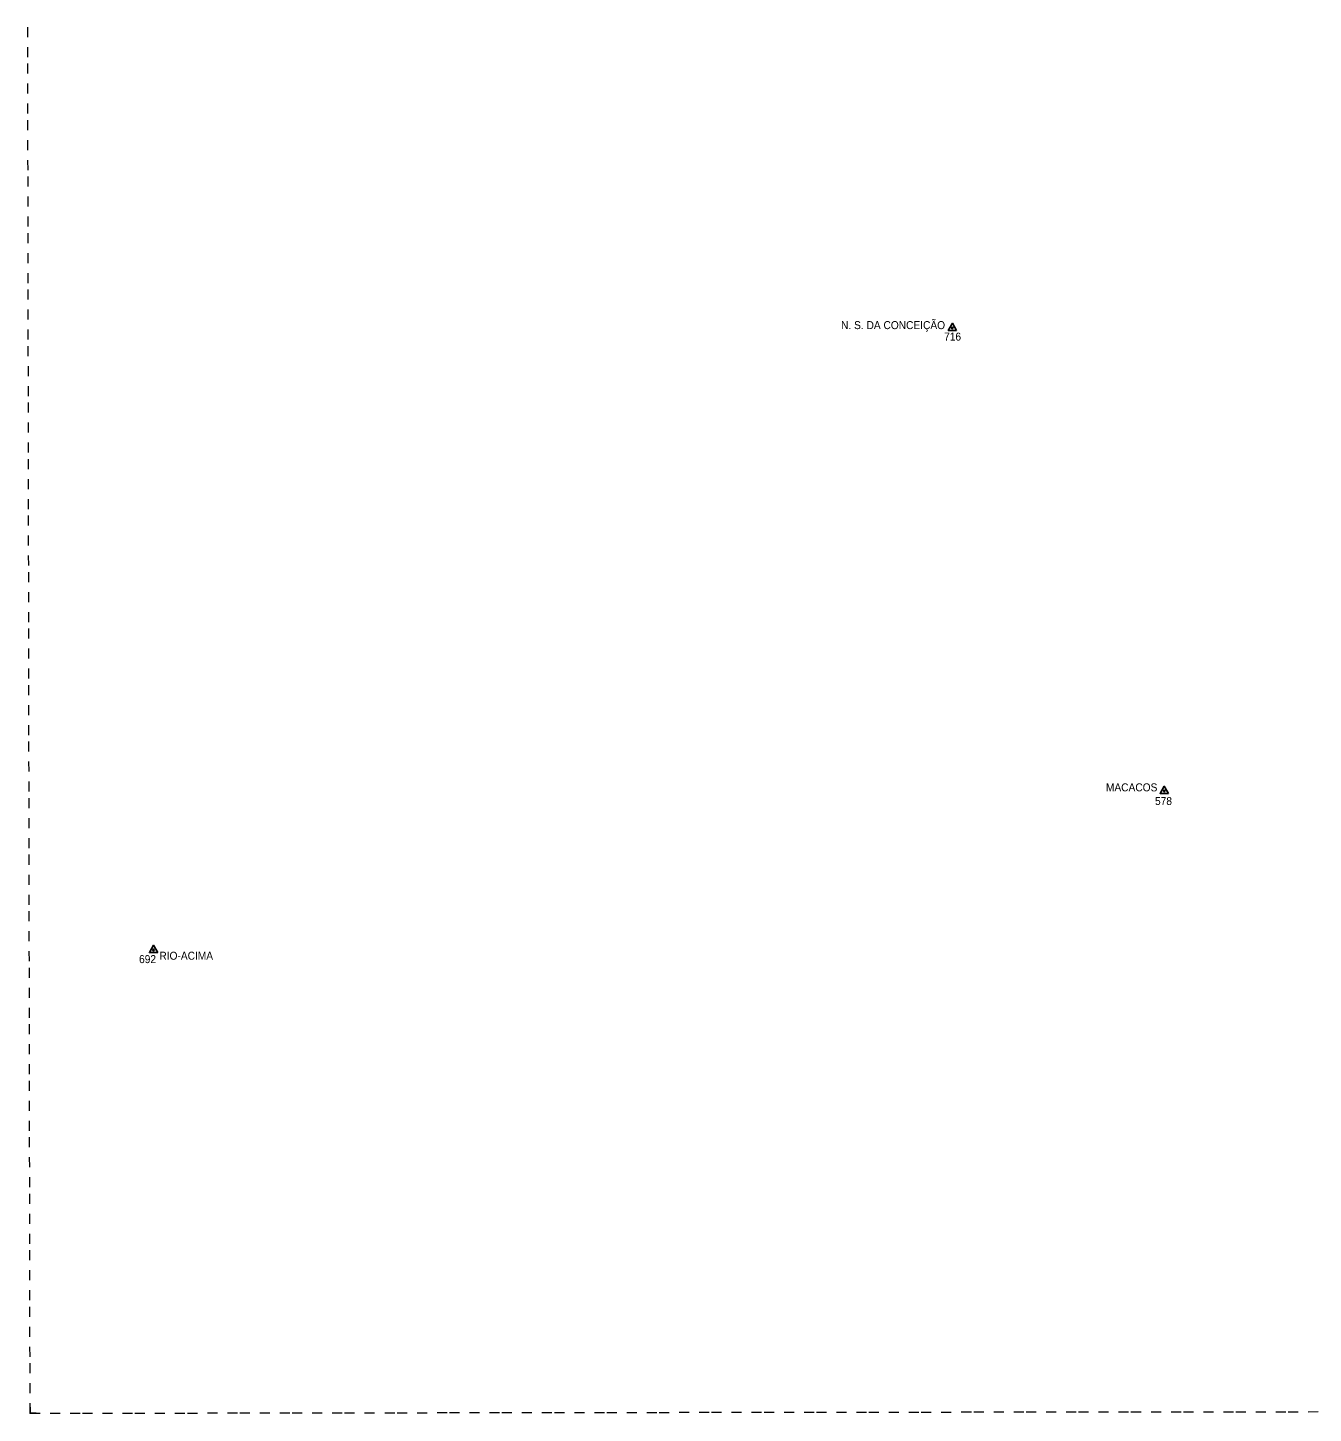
# Model space of a CAD drawing. Extents: x 474.3 to 500, y 7484.1 to 7511.8.
# Drawn here: x 474.31 to 487.15, y 7484.1 to 7497.95 of the extents above; entities that cross this region are included whole.
import ezdxf
from ezdxf.enums import TextEntityAlignment as Align

# ---------------------------------------------------------------- set-up
doc = ezdxf.new("R2010")
doc.units = 0
doc.header["$LTSCALE"] = 0.032
doc.header["$PDMODE"] = 32
doc.header["$PDSIZE"] = 0.016
doc.linetypes.add('SHORT_DASHED', pattern=[2.7, 1.5, -1.2])
for name, color, linetype, lineweight in [('1', 7, 'SHORT_DASHED', 13), ('46', 7, 'Continuous', 25), ('63', 7, 'Continuous', 25)]:
    doc.layers.add(name, color=color, linetype=linetype, lineweight=lineweight)
doc.layers.add('61', color=7, linetype='Continuous')

msp = doc.modelspace()

# ---------------------------------------------------------------- linework, layer by layer
at = {"layer": '1'}
for points in [[(474.3315, 7484.1002), (474.3306, 7484.665), (474.3296, 7485.2298), (474.3286, 7485.7946), (474.3277, 7486.3594), (474.3267, 7486.9242), (474.3258, 7487.489), (474.3248, 7488.0538), (474.3239, 7488.6185), (474.3229, 7489.1833), (474.322, 7489.7481), (474.321, 7490.3129), (474.3201, 7490.8777), (474.3191, 7491.4425), (474.3182, 7492.0073), (474.3172, 7492.572), (474.3163, 7493.1368), (474.3153, 7493.7016), (474.3144, 7494.2664), (474.3134, 7494.8312), (474.3125, 7495.396), (474.3115, 7495.9607), (474.3106, 7496.5255), (474.3096, 7497.0903), (474.3087, 7497.6551), (474.3077, 7498.2199)], [(474.3315, 7484.1002), (474.8554, 7484.1011), (475.3792, 7484.102), (475.9031, 7484.1028), (476.4269, 7484.1036), (476.9507, 7484.1044), (477.4746, 7484.1052), (477.9984, 7484.106), (478.5223, 7484.1067), (479.0461, 7484.1075), (479.57, 7484.1082), (480.0938, 7484.1089), (480.6177, 7484.1095), (481.1415, 7484.1102), (481.6654, 7484.1108), (482.1892, 7484.1115), (482.7131, 7484.1121), (483.2369, 7484.1127), (483.7608, 7484.1132), (484.2846, 7484.1138), (484.8084, 7484.1143), (485.3323, 7484.1148), (485.8561, 7484.1153), (486.38, 7484.1158), (486.9038, 7484.1162), (487.4277, 7484.1167)]]:
    msp.add_lwpolyline(points, dxfattribs=at)
at = {"layer": '46'}
for points in [[(483.5893, 7494.9226), (483.5476, 7494.995), (483.5057, 7494.9226)], [(485.7064, 7490.2949), (485.6647, 7490.3673), (485.6228, 7490.2949)], [(475.6066, 7488.7054), (475.5649, 7488.7778), (475.523, 7488.7054)]]:
    msp.add_lwpolyline(points, close=True, dxfattribs=at)
for p in [(483.5475, 7494.9468), (485.6646, 7490.3191), (475.5648, 7488.7296)]:
    msp.add_point(p, dxfattribs=at)
at = {"layer": '63'}
msp.add_lwpolyline([(474.3315, 7484.1618), (474.3315, 7484.1002), (474.3922, 7484.1002)], dxfattribs=at)

# ---------------------------------------------------------------- texts
at = {"layer": '61', "width": 0.95}
for s, p in [('N. S. DA CONCEIÇÃO', (483.4745, 7494.9358)), ('MACACOS', (485.5959, 7490.316))]:
    msp.add_text(s, height=0.08, dxfattribs=at).set_placement(p, align=Align.RIGHT)
for s, p in [('716', (483.4648, 7494.8207)), ('578', (485.5723, 7490.1794)), ('692', (475.4203, 7488.5993)), ('RIO-ACIMA', (475.6234, 7488.6333))]:
    msp.add_text(s, height=0.08, dxfattribs=at).set_placement(p)

doc.saveas('drawing.dxf')
